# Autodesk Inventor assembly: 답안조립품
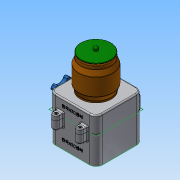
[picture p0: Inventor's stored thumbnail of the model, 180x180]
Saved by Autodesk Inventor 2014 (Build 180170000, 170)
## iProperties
Created: 2018-01
Part Number: 답안조립품
Document SubType Name: Assembly
Designer: 601-25
Author: 601-25
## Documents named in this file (9)
- C:\Users\601-25\Desktop\480108V1027\답안조립품.iam
- C:\Users\601-25\Desktop\480108V1027\본체.ipt
- C:\Users\601-25\Desktop\480108V1027\본체커버.ipt
- C:\Users\601-25\Desktop\480108V1027\볼트 M3x12.ipt
- C:\Users\601-25\Desktop\480108V1027\볼트 M4x12.ipt
- C:\Users\601-25\Desktop\480108V1027\용기.ipt
- C:\Users\601-25\Desktop\480108V1027\용기캡.ipt
- C:\Users\601-25\Desktop\480108V1027\핸들.ipt
- C:\Users\601-25\Desktop\480108V1027\핸들축.ipt
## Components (2 placed, 2 different names)
1. 핸들:1
2. 핸들축:1
